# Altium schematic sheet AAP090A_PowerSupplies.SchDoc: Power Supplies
size 431 x 279 mm; Date: Not shown in title block; ApprovedBy: Not shown in title block; CheckedBy: Not shown in title block; Author: Not shown in title block; CompanyName: Not shown in title block; DrawnBy: LDN; Engineer: Not shown in title block; Organization: Not shown in title block; Address1: Not shown in title block; Address2: Not shown in title block; Address3: Not shown in title block; Address4: Not shown in title block; DocumentNumber: 5; Revision: Use project parameter SCH_Rev; SheetNumber: 5; SheetTotal: 6; PageSetup: Record=PageOptions¦CenterHorizontal=True¦CenterVertical=True¦PrintScale=1.00¦XCorrection=1.00¦YCorrection=1.00¦PrintKind=0¦BorderSize=5000000¦LeftOffset=0¦BottomOffset=0¦Orientation=2¦PaperLength=1000¦PaperWidth=1000¦Scale=100¦PaperSource=15¦PrintQuality=600¦MediaType=1¦DitherType=10¦PaperKind=Letter¦PrintScaleMode=1
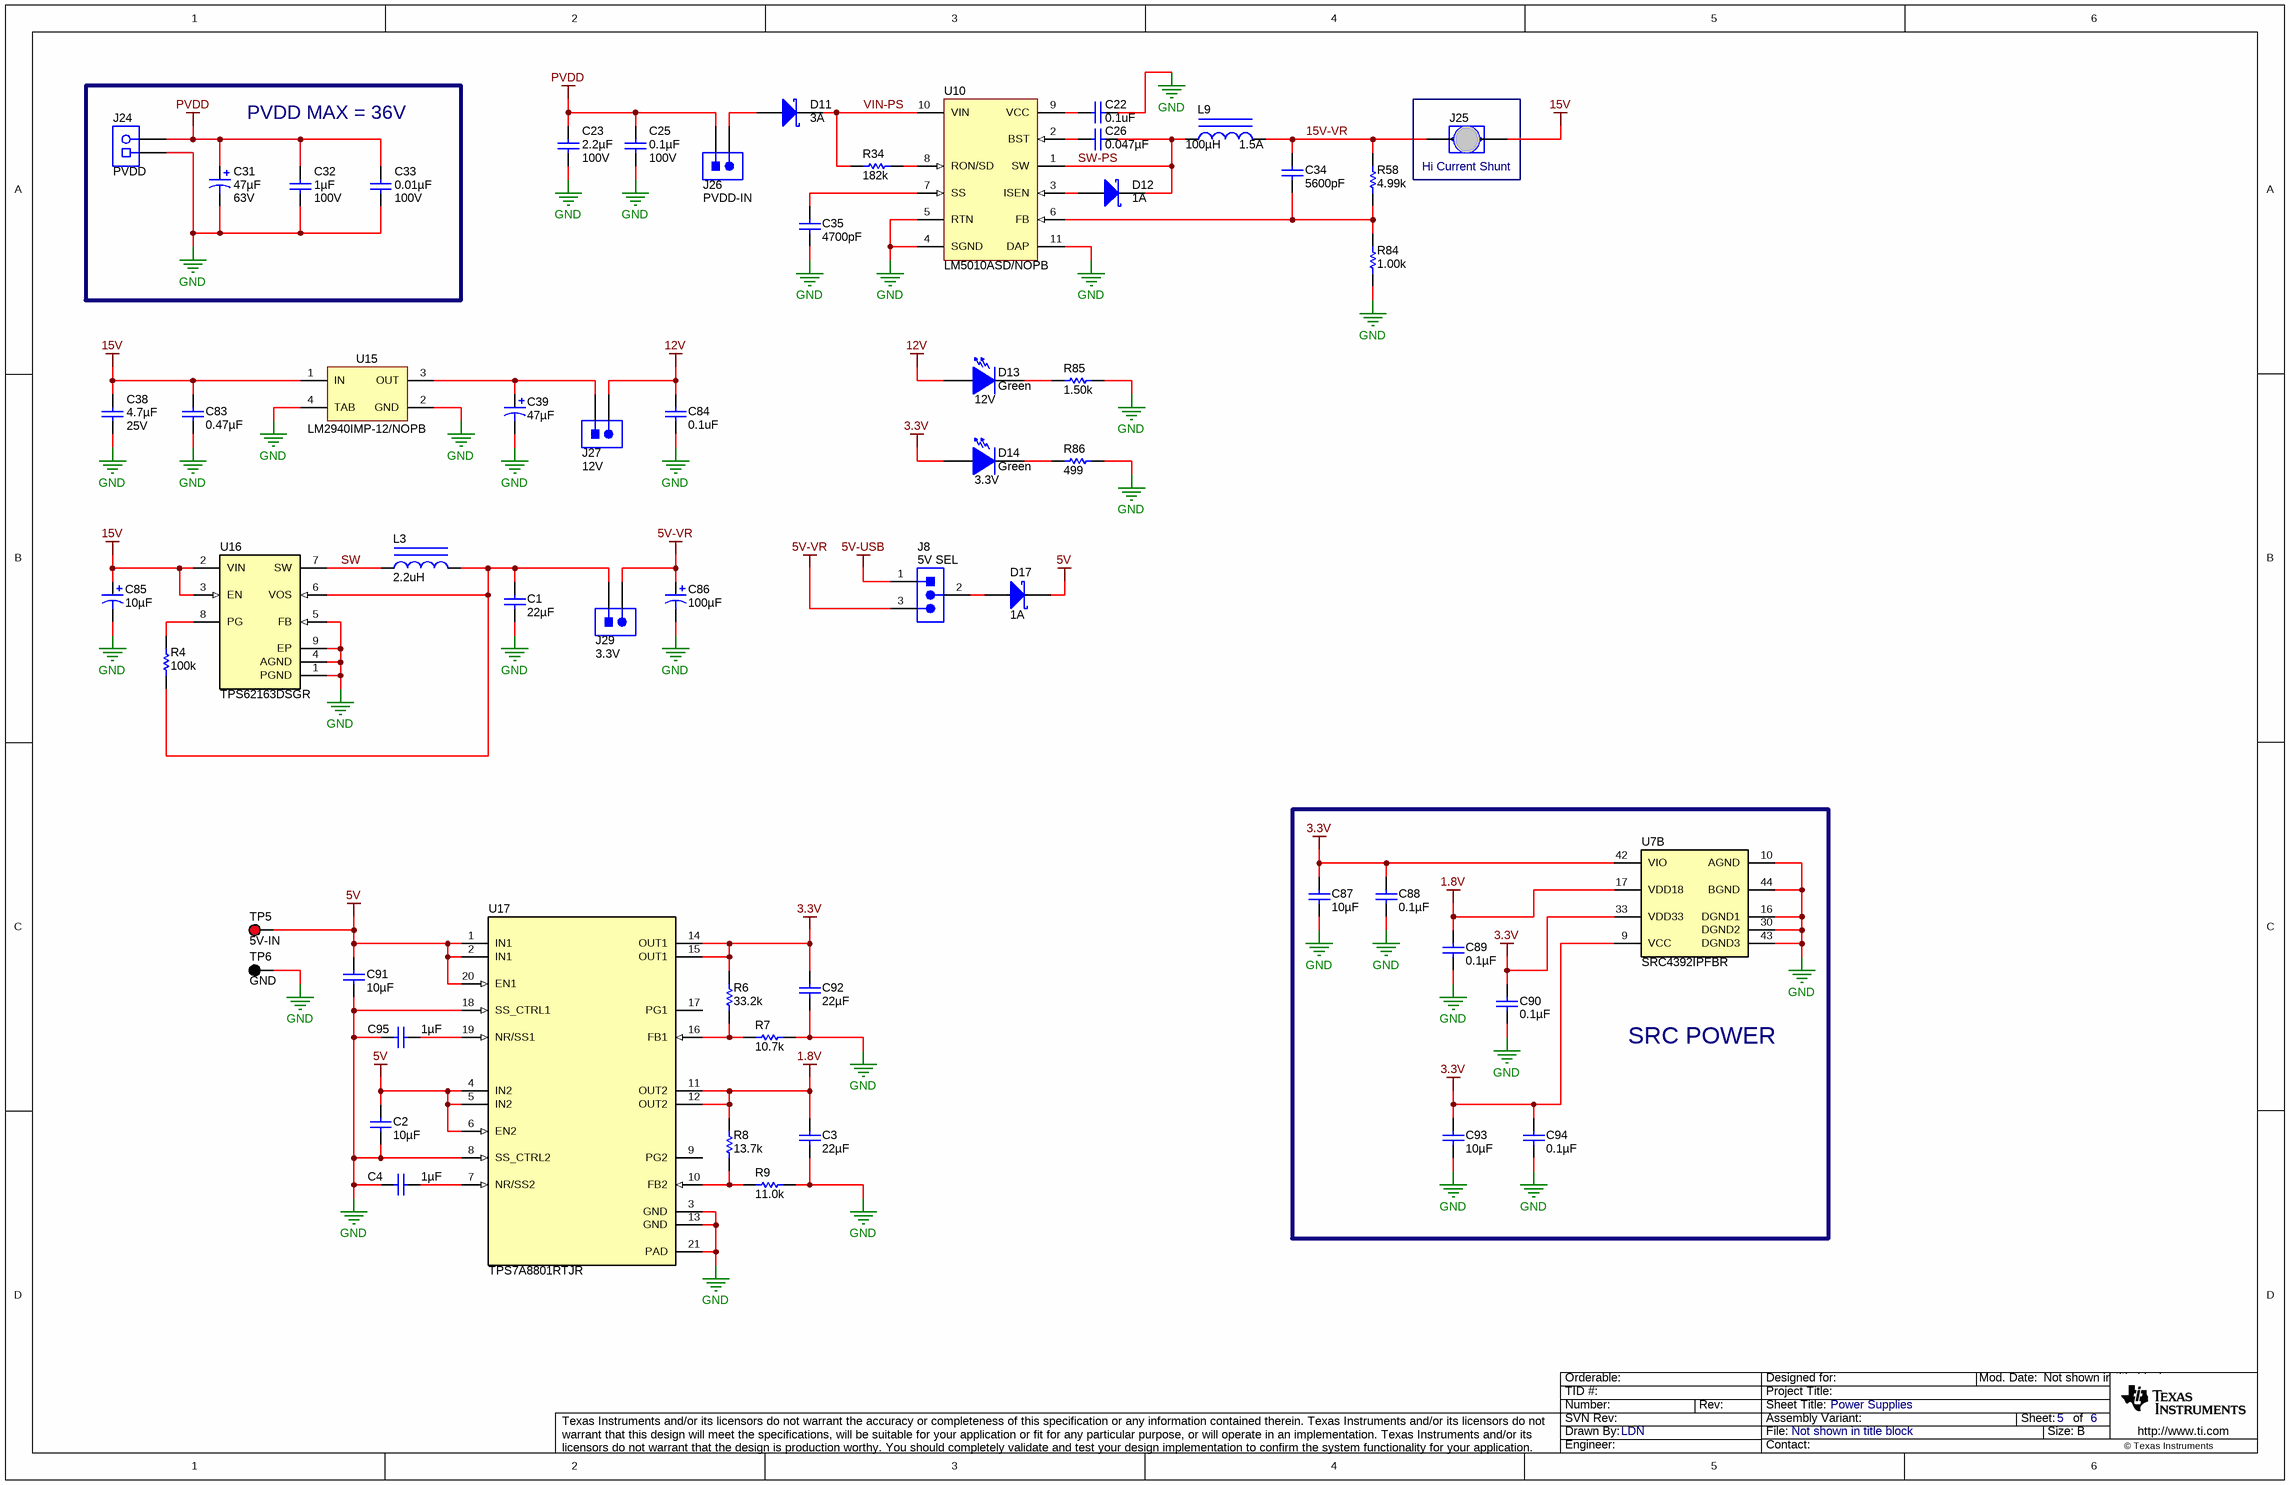
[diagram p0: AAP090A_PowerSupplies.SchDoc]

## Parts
C1  ValueDisplayed: 22µF  [0805_KTR]  (hidden comment: GRM21BZ71A226ME15L)
C2  ValueDisplayed: 10µF  [0603L]  (hidden comment: GRM188R61A106ME69D)
C3  ValueDisplayed: 22µF  [0805_KTR]  (hidden comment: GRM21BZ71A226ME15L)
C4  ValueDisplayed: 1µF  [0603L]  (hidden comment: GRM188R71C105KA12D)
C22  value 0.1uF  [0603L]  (hidden comment: C0603C104K5RACTU)
C23  ValueDisplayed: 2.2µF  Value2: 100V  [1210_210L]  (hidden comment: C1210C225K1RACTU)
C25  ValueDisplayed: 0.1µF  Value2: 100V  [0603L]  (hidden comment: GRM188R72A104KA35J)
C26  ValueDisplayed: 0.047µF  [0402L]  (hidden comment: GRM155R71E473KA88D)
C31  ValueDisplayed: 47µF  Value2: 63V  [SM_RADIAL_F]  (hidden comment: +)
C32  ValueDisplayed: 1µF  Value2: 100V  [1206_180L]  (hidden comment: GRM31CR72A105KA01L)
C33  ValueDisplayed: 0.01µF  Value2: 100V  [0603L]  (hidden comment: 06031C103KAT2A)
C34  ValueDisplayed: 5600pF  [0603L]  (hidden comment: GRM188R71H562KA01D)
C35  ValueDisplayed: 4700pF  [0603L]  (hidden comment: C0603X472K5RACTU)
C38  ValueDisplayed: 4.7µF  Value2: 25V  [1206_180L]  (hidden comment: GRM31CR71E475KA88L)
C39  ValueDisplayed: 47µF  [SM_RADIAL_D]  (hidden comment: +)
C83  ValueDisplayed: 0.47µF  [0603L]  (hidden comment: GRM188R71E474KA12D)
C84  value 0.1uF  [0603L]  (hidden comment: C0603C104K5RACTU)
C85  ValueDisplayed: 10µF  [SM_RADIAL_B]  (hidden comment: +)
C86  ValueDisplayed: 100µF  [SM_RADIAL_C]  (hidden comment: +)
C87  ValueDisplayed: 10µF  [0603L]  (hidden comment: GRM188R61A106ME69D)
C88  ValueDisplayed: 0.1µF  [0402L]  (hidden comment: GRM155R71A104KA01D)
C89  ValueDisplayed: 0.1µF  [0402L]  (hidden comment: GRM155R71A104KA01D)
C90  ValueDisplayed: 0.1µF  [0402L]  (hidden comment: GRM155R71A104KA01D)
C91  ValueDisplayed: 10µF  [0603L]  (hidden comment: GRM188R61A106ME69D)
C92  ValueDisplayed: 22µF  [0805_KTR]  (hidden comment: GRM21BZ71A226ME15L)
C93  ValueDisplayed: 10µF  [0603L]  (hidden comment: GRM188R61A106ME69D)
C94  ValueDisplayed: 0.1µF  [0402L]  (hidden comment: GRM155R71A104KA01D)
C95  ValueDisplayed: 1µF  [0603L]  (hidden comment: GRM188R71C105KA12D)
D11  Value1: 3A  [SMA]  (hidden comment: SK310A-TP)
D12  Value1: 1A  [SMA]  (hidden comment: B1100-13-F)
D13  12V  value Green  [LED_LTST-C171]
D14  3.3V  value Green  [LED_LTST-C171]
D17  Value1: 1A  [SMA]  (hidden comment: B1100-13-F)
J8  5V SEL  [PBC03SAAN]
J24  PVDD  [Pomona_6883]
J25  S1911-46R  [HARWIN_S1911-46R]  (value not drawn)
J26  PVDD-IN  [Sullins_PBC02SAAN]
J27  12V  [Sullins_PBC02SAAN]
J29  3.3V  [Sullins_PBC02SAAN]
L3  ValueDisplayed: 2.2uH  [VLCF4020]  (hidden comment: VLCF4020T-2R2N1R7)
L9  ValueDisplayed: 100µH  Value2: 1.5A  [WE-PD_1050]  (hidden comment: 7447714101)
R4  ValueDisplayed: 100k  [0603L]  (hidden comment: RC0603FR-07100KL)
R6  ValueDisplayed: 33.2k  [0603L]  (hidden comment: RC0603FR-0733K2L)
R7  ValueDisplayed: 10.7k  [0603L]  (hidden comment: RC0603FR-0710K7L)
R8  ValueDisplayed: 13.7k  [0603L]  (hidden comment: RC0603FR-0713K7L)
R9  ValueDisplayed: 11.0k  [0603L]  (hidden comment: RC0603FR-0711KL)
R34  ValueDisplayed: 182k  [0805_KTR]  (hidden comment: ERJ-6ENF1823V)
R58  ValueDisplayed: 4.99k  [0402L]  (hidden comment: RC0402FR-074K99L)
R84  ValueDisplayed: 1.00k  [0402L]  (hidden comment: RC0402FR-071KL)
R85  ValueDisplayed: 1.50k  [0603L]  (hidden comment: RC0603FR-071K5L)
R86  ValueDisplayed: 499  [0603L]  (hidden comment: RC0603FR-07499RL)
TP5  5V-IN  [Keystone5010]
TP6  GND  [Keystone5011]
U7  SRC4392IPFBR  [PFB0048A_N]  (part B of 2)
U10  LM5010ASD/NOPB  [SDC10A]
U15  LM2940IMP-12/NOPB  [MP04A_N]
U16  TPS62163DSGR  [DSG0008A]
U17  TPS7A8801RTJR  [RTJ0020D]

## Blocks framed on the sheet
PVDD MAX = 36V: C31-C33 J24
Hi Current Shunt: J25
SRC POWER: C87-C90 C93 C94 U7

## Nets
1.8V: C3.1 C89.2 R8.1 U7.17(VDD18) U17.11(OUT2) U17.12(OUT2)
3.3V: C87.1 C88.2 C90.2 C92.1 C93.1 C94.2 D14.1(A) R6.1 U7.9(VCC) U7.33(VDD33) U7.42(VIO) U17.14(OUT1) U17.15(OUT1)
5V: C2.1 C91.1 D17.1(K) TP5.1 U17.1(IN1) U17.2(IN1) U17.4(IN2) U17.5(IN2) U17.6(EN2) U17.20(EN1)
5V-USB: J8.1
5V-VR: C86.1(+) J8.3 J29.2
12V: C84.2 D13.1(A) J27.2
15V: C38.1 C83.1 C85.1(+) J25.2 U15.1(IN) U16.2(VIN) U16.3(EN)
GND: C1.2 C2.2 C3.2 C4.1 C22.2 C23.2 C25.2 C31.2(-) C32.1 C33.2 C35.2 C38.2 C39.2(-) C83.2 C84.1 C85.2(-) C86.2(-) C87.2 C88.1 C89.1 C90.1 C91.2 C92.2 C93.2 C94.1 C95.1 J24.1 R7.1 R9.1 R84.1 R85.2 R86.2 TP6.1 U7.10(AGND) U7.16(DGND1) U7.30(DGND2) U7.43(DGND3) U7.44(BGND) U10.4(SGND) U10.5(RTN) U10.11(DAP) U15.2(GND) U15.4(TAB) U16.1(PGND) U16.4(AGND) U16.5(FB) U16.9(EP) U17.3(GND) U17.8(SS_CTRL2) U17.13(GND) U17.18(SS_CTRL1) U17.21(PAD)
PVDD: C23.1 C25.1 C31.1(+) C32.2 C33.1 J24.2 J26.1
15V-VR: C34.1 J25.1 L9.2 R58.2
SW: L3.1 U16.7(SW)
SW-PS: C26.2 D12.1(K) L9.1 U10.1(SW)
VIN-PS: D11.1(K) R34.1 U10.10(VIN)
NetC1_1: C1.1 J29.1 L3.2 R4.1 U16.6(VOS)
NetC4_2: C4.2 U17.7(NR/SS2)
NetC22_1: C22.1 U10.9(VCC)
NetC26_1: C26.1 U10.2(BST)
NetC34_2: C34.2 R58.1 R84.2 U10.6(FB)
NetC35_1: C35.1 U10.7(SS)
NetC39_1: C39.1(+) J27.1 U15.3(OUT)
NetC95_2: C95.2 U17.19(NR/SS1)
NetD11_2: D11.2(A) J26.2
NetD12_2: D12.2(A) U10.3(ISEN)
NetD13_2: D13.2(K) R85.1
NetD14_2: D14.2(K) R86.1
NetD17_2: D17.2(A) J8.2
NetR4_2: R4.2 U16.8(PG)
NetR6_2: R6.2 R7.2 U17.16(FB1)
NetR8_2: R8.2 R9.2 U17.10(FB2)
NetR34_2: R34.2 U10.8(RON/SD)

Not connected (* = marked no-connect by the designer): U17 9(PG2) 17(PG1)

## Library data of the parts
C1 C3 C92 = GRM21BZ71A226ME15L: CAP, CERM, 22 µF, 10 V, +/- 20%, X7R, 0805; Manufacturer: MuRata; Polarized: N; CompType: Capacitor; Value: 22uF; U/M: EA; Cap_F: 0.000022; Tolerance_%: 20; Value1: Unknown; VDC_V: 10; Value2: 10V; TaMin_C: -55; TaMax_C: 125; Cap_Case: 0805; AEC Category: Q200
C2 C87 C91 C93 = GRM188R61A106ME69D: CAP, CERM, 10 µF, 10 V, +/- 20%, X5R, 0603; Manufacturer: MuRata; Polarized: N; CompType: Capacitor; Value: 10uF; U/M: EA; Cap_F: 0.00001; Tolerance_%: 20; Value1: Unknown; VDC_V: 10; Value2: 10V; TaMin_C: -55; TaMax_C: 85; Cap_Case: 0603; AEC Category: Q200
C4 C95 = GRM188R71C105KA12D: CAP, CERM, 1 µF, 16 V, +/- 10%, X7R, 0603; Manufacturer: MuRata; Polarized: N; CompType: Capacitor; Value: 1uF; U/M: EA; Cap_F: 0.000001; Tolerance_%: 10; ESR_ohm: 0.011; Value1: 0.011 ohm; VDC_V: 16; Value2: 16V; TaMin_C: -55; TaMax_C: 125; Cap_Case: 0603; AEC Category: Q200
C22 C84 = C0603C104K5RACTU: CAP, CERM, 0.1 µF, 50 V, +/- 10%, X7R, 0603; Manufacturer: Kemet; Polarized: N; CompType: Capacitor; ValueDisplayed: 0.1µF; U/M: EA; Cap_F: 0.0000001; Tolerance_%: 10; Value1: Unknown; VDC_V: 50; Value2: 50V; TaMin_C: -55; TaMax_C: 125; Cap_Case: 0603; AEC Category: Q200
C23 = C1210C225K1RACTU: CAP, CERM, 2.2 µF, 100 V, +/- 10%, X7R, 1210; Manufacturer: Kemet; Polarized: N; CompType: Capacitor; Value: 2.2uF; U/M: EA; Cap_F: 0.0000022; Tolerance_%: 10; Value1: Unknown; VDC_V: 100; TaMin_C: -55; TaMax_C: 125; Cap_Case: 1210; SizeArea_mm2: 8; SizeAreaWB_mm2: 14.7; SizeX_mm: 3.2; SizeY_mm: 2.5; SizeZ_mm: 2.1; AEC Category: Q200
C25 = GRM188R72A104KA35J: CAP, CERM, 0.1 µF, 100 V, +/- 10%, X7R, 0603; Manufacturer: MuRata; Polarized: N; CompType: Capacitor; Value: 0.1uF; U/M: EA; Cap_F: 0.0000001; Tolerance_%: 10; Value1: Unknown; VDC_V: 100; TaMin_C: -55; TaMax_C: 125; Cap_Case: 0603; AEC Category: Q200
C26 = GRM155R71E473KA88D: CAP, CERM, 0.047 µF, 25 V, +/- 10%, X7R, 0402; Manufacturer: MuRata; Polarized: N; CompType: Capacitor; Value: 0.047uF; U/M: EA; Cap_F: 0.000000047; Tolerance_%: 10; Value1: Unknown; VDC_V: 25; Value2: 25V; TaMin_C: -55; TaMax_C: 125; Cap_Case: 0402; AEC Category: Q200
C31 = EEE-FK1J470P: CAP, AL, 47 µF, 63 V, +/- 20%, 0.65 ohm, SMD; Manufacturer: Panasonic; Polarized: Y; CompType: Capacitor; Value: 47uF; U/M: EA; Cap_F: 0.000047; Tolerance_%: 20; VDC_V: 63; ESR_ohm: 0.65; IRMS_A: 0.25; TaMin_C: -55; TaMax_C: 105; Cap_Case: F; AEC Category: Q200
C32 = GRM31CR72A105KA01L: CAP, CERM, 1 µF, 100 V, +/- 10%, X7R, 1206; Manufacturer: MuRata; Polarized: N; CompType: Capacitor; Value: 1uF; U/M: EA; Cap_F: 0.000001; Tolerance_%: 10; Value1: Unknown; VDC_V: 100; TaMin_C: -55; TaMax_C: 125; Cap_Case: 2220; SizeArea_mm2: 5.12; SizeAreaWB_mm2: 10.92; SizeX_mm: 3.2; SizeY_mm: 1.6; SizeZ_mm: 1.8; AEC Category: Q200
C33 = 06031C103KAT2A: CAP, CERM, 0.01 µF, 100 V, +/- 10%, X7R, 0603; Manufacturer: AVX; Polarized: N; CompType: Capacitor; Value: 0.01uF; U/M: EA; Cap_F: 0.00000001; Tolerance_%: 10; ESR_ohm: 0.098; Value1: 0.098 ohm; VDC_V: 100; TaMin_C: -55; TaMax_C: 125; Cap_Case: 0603; AEC Category: Q200
C34 = GRM188R71H562KA01D: CAP, CERM, 5600 pF, 50 V, +/- 10%, X7R, 0603; Manufacturer: MuRata; Polarized: N; CompType: Capacitor; Value: 5600pF; U/M: EA; Cap_F: 0.0000000056; Tolerance_%: 10; Value1: Unknown; VDC_V: 50; Value2: 50V; TaMin_C: -55; TaMax_C: 125; Cap_Case: 0603; AEC Category: Q200
C35 = C0603X472K5RACTU: CAP, CERM, 4700 pF, 50 V, +/- 10%, X7R, 0603; Manufacturer: Kemet; Polarized: N; CompType: Capacitor; Value: 4700pF; U/M: EA; Cap_F: 0.0000000047; Tolerance_%: 10; Value1: Unknown; VDC_V: 50; Value2: 50V; TaMin_C: -55; TaMax_C: 125; Cap_Case: 0603; AEC Category: Q200
C38 = GRM31CR71E475KA88L: CAP, CERM, 4.7 µF, 25 V, +/- 10%, X7R, 1206; Manufacturer: MuRata; Polarized: N; CompType: Capacitor; Value: 4.7uF; U/M: EA; Cap_F: 0.0000047; Tolerance_%: 10; Value1: Unknown; VDC_V: 25; TaMin_C: -55; TaMax_C: 125; Cap_Case: 1206; SizeArea_mm2: 5.12; SizeAreaWB_mm2: 10.92; SizeX_mm: 3.2; SizeY_mm: 1.6; SizeZ_mm: 1.8; AEC Category: Q200
C39 = EEE-FK1C470P: CAP, AL, 47 µF, 16 V, +/- 20%, 0.36 ohm, SMD; Manufacturer: Panasonic; Polarized: Y; CompType: Capacitor; Value: 47uF; U/M: EA; Cap_F: 0.000047; Tolerance_%: 20; VDC_V: 16; Value2: 16V; ESR_ohm: 0.36; IRMS_A: 0.24; TaMin_C: -55; TaMax_C: 105; Cap_Case: D; AEC Category: Q200
C83 = GRM188R71E474KA12D: CAP, CERM, 0.47 µF, 25 V, +/- 10%, X7R, 0603; Manufacturer: MuRata; Polarized: N; CompType: Capacitor; Value: 0.47uF; U/M: EA; Cap_F: 0.00000047; Tolerance_%: 10; Value1: Unknown; VDC_V: 25; Value2: 25V; TaMin_C: -55; TaMax_C: 125; Cap_Case: 0603; AEC Category: Q200
C85 = EEE-FK1C100R: CAP, AL, 10 µF, 16 V, +/- 20%, 1.35 ohm, SMD; Manufacturer: Panasonic; Polarized: Y; CompType: Capacitor; Value: 10uF; U/M: EA; Cap_F: 0.00001; Tolerance_%: 20; VDC_V: 16; Value2: 16V; ESR_ohm: 1.35; IRMS_A: 0.09; TaMin_C: -55; TaMax_C: 105; Cap_Case: B; AEC Category: Q200
C86 = EEE-FK0J101UR: CAP, AL, 100 µF, 6.3 V, +/- 20%, 0.7 ohm, SMD; Manufacturer: Panasonic; Polarized: Y; CompType: Capacitor; Value: 100uF; U/M: EA; Cap_F: 0.0001; Tolerance_%: 20; Value1: 0.7 ohm; VDC_V: 6.3; Value2: 6.3V; ESR_ohm: 0.7; IRMS_A: 0.16; TaMin_C: -55; TaMax_C: 105; Cap_Case: C; AEC Category: Q200
C88-C90 C94 = GRM155R71A104KA01D: CAP, CERM, 0.1 µF, 10 V, +/- 10%, X7R, 0402; Manufacturer: MuRata; Polarized: N; CompType: Capacitor; Value: 0.1uF; U/M: EA; Cap_F: 0.0000001; Tolerance_%: 10; Value1: Unknown; Value2: 10V; TaMin_C: -55; TaMax_C: 125; Cap_Case: 0402; AEC Category: Q200
D11 = SK310A-TP: Diode, Schottky, 100 V, 3 A, SMA; Manufacturer: Micro Commercial Components; U/M: EA; Vf_V: 0.85; Value: 100V; Value2: 0.85V; Io_A: 3; Vr_V: 100; TJmax_C: 125; RJC_CperW: 10; AEC Category: Q101
D12 D17 = B1100-13-F: Diode, Schottky, 100 V, 1 A, SMA; Manufacturer: Diodes Inc.; U/M: EA; Vf_V: 0.79; Value: 100V; Value2: 0.79V; Io_A: 1; Vr_V: 100; TJmax_C: 150; RJC_CperW: 25; AEC Category: Q101
D13 D14 = LTST-C171GKT: LED, Green, SMD; Manufacturer: Lite-On; Type: AlInGaP; Vf_V: 2.1; Value2: 2.1V; Io_A: 20; Value1: W; U/M: EA
J8 = PBC03SAAN: Header, 100mil, 3x1, Gold, TH; Manufacturer: Sullins Connector Solutions; SymbolCreator: a0799628; Green_Lifecycle: Not Set; Green_REACh: Incomplete
J24 = CMP-0075104-1: Dual Binding Posts with Base, 2x1, TH; Manufacturer: Pomona Electronics; PartNumber: 6883; CNHeader: False; Green_Lifecycle: Not Set; Green_REACh: Incomplete; CompType: Connector
J25 = CMP-0075020-1: JUMPER TIN SMD; Manufacturer: Harwin; CNHeader: False; Green_Lifecycle: Active; Green_REACh: Passed; CompType: Jumper SMT
J26 J27 J29 = PBC02SAAN: Header, 100mil, 2x1, Gold, TH; Manufacturer: Sullins Connector Solutions; SymbolCreator: a0412235; Pitch_mm: 2.54; Gender: Male; Shrouded: N; Row_Count: 1; Current_A: 3; Voltage_V: 1800; Cert_UL: Y
L3 = CMP-0062895-1: Inductor, Shielded, Ferrite, 2.2 uH, 1.72 A, 0.059 ohm, SMD; Manufacturer: TDK; Isat: 1.72A @ 30% inductance drop; Irms: 2.19A @ 40C rise; Green_Lifecycle: Active; SizeAreaWB_mm2: 25; DCR_ohm: 0.059; Green_REACh: Passed; Value: 2.2uH; Imax_A: 1.72A; SizeZ_mm: 2; SizeX_mm: 4; SizeArea_mm2: 16; Ind_H: 2.2µH; AEC Category: Q200
L9 = 7447714101: Inductor, Shielded Drum Core, Ferrite, 100 µH, 1.5 A, 0.165 ohm, SMD; Manufacturer: Wurth Elektronik; Value: 100uH; Ind_H: 100.0E-6; Imax_A: 1.5; Irms: 1.5A @ 40C rise; Isat: 1.75A @ 10% inductance drop; DCR_ohm: 0.165; AEC Category: Q200
R4 = RC0603FR-07100KL: RES, 100 k, 1%, 0.1 W, 0603; Manufacturer: Yageo America; CompType: Resistor; Value: 100k; Res_ohm: 100000; Tolerance_%: 1; Power_W: 0.1; Value2: 0.1W; VDC_V: 150; TempCo: 200 ppm/C; EIA_Code: E96; U/M: EA; AEC Category: Q200; SizeArea_mm2: 1.28; SizeX_mm: 1.6; SizeY_mm: 0.8; Green_Lifecycle: Active; Green_REACh: Passed
R6 = RC0603FR-0733K2L: RES, 33.2 k, 1%, 0.1 W, 0603; Manufacturer: Yageo America; CompType: Resistor; Value: 33.2k; Res_ohm: 33200; Value_Code: 33k2; Tolerance_%: 1; Power_W: 0.1; Value2: 0.1W; VDC_V: 150; TempCo: 200 ppm/C; EIA_Code: E96; U/M: EA; AEC Category: Q200; SizeArea_mm2: 1.28; SizeX_mm: 1.6; SizeY_mm: 0.8; Green_Lifecycle: Active; Green_REACh: Passed
R7 = RC0603FR-0710K7L: RES, 10.7 k, 1%, 0.1 W, 0603; Manufacturer: Yageo America; CompType: Resistor; Value: 10.7k; Res_ohm: 10700; Value_Code: 10k7; Tolerance_%: 1; Power_W: 0.1; Value2: 0.1W; VDC_V: 150; TempCo: 200 ppm/C; EIA_Code: E96; U/M: EA; AEC Category: Q200; SizeArea_mm2: 1.28; SizeX_mm: 1.6; SizeY_mm: 0.8
R8 = RC0603FR-0713K7L: RES, 13.7 k, 1%, 0.1 W, 0603; Manufacturer: Yageo America; CompType: Resistor; Value: 13.7k; Res_ohm: 13700; Value_Code: 13k7; Tolerance_%: 1; Power_W: 0.1; Value2: 0.1W; VDC_V: 150; TempCo: 200 ppm/C; EIA_Code: E96; U/M: EA; AEC Category: Q200; SizeArea_mm2: 1.28; SizeX_mm: 1.6; SizeY_mm: 0.8; Green_Lifecycle: Active; Green_REACh: Passed
R9 = RC0603FR-0711KL: RES, 11.0 k, 1%, 0.1 W, 0603; Manufacturer: Yageo America; CompType: Resistor; Value: 11.0k; Res_ohm: 11000; Value_Code: 11k0; Tolerance_%: 1; Power_W: 0.1; Value2: 0.1W; VDC_V: 150; TempCo: 200 ppm/C; EIA_Code: E96; U/M: EA; AEC Category: Q200; SizeArea_mm2: 1.28; SizeX_mm: 1.6; SizeY_mm: 0.8; Green_Lifecycle: Active; Green_REACh: Passed
R34 = ERJ-6ENF1823V: RES, 182 k, 1%, 0.125 W, 0805; Manufacturer: Panasonic; CompType: Resistor; Value: 182k; Res_ohm: 182000; Tolerance_%: 1; Power_W: 0.125; Value2: 0.125W; TempCo: 100 ppm/C; EIA_Code: E96; U/M: EA; AEC Category: Q200
R58 = RC0402FR-074K99L: RES, 4.99 k, 1%, 0.063 W, 0402; Manufacturer: Yageo America; CompType: Resistor; Value: 4.99k; Res_ohm: 4990; Value_Code: 4k99; Tolerance_%: 1; Power_W: 0.063; Value2: 0.063W; VDC_V: 50; TempCo: 100 ppm/C; EIA_Code: E96; U/M: EA; AEC Category: Q200; AEC Qualified: N; SizeArea_mm2: 0.5; SizeZ_mm: 0.6; Green_Lifecycle: Active; Green_REACh: Passed
R84 = RC0402FR-071KL: RES, 1.00 k, 1%, 0.0625 W, 0402; Manufacturer: Yageo America; CompType: Resistor; Value: 1.00k; Res_ohm: 1000; Value_Code: 1k00; Tolerance_%: 1; Power_W: 0.0625; VDC_V: 50; TempCo: 100 ppm/C; EIA_Code: E96; U/M: EA; AEC Category: Q200; AEC Qualified: N; SizeArea_mm2: 0.5; SizeZ_mm: 0.6; Green_Lifecycle: Active; Green_REACh: Passed
R85 = RC0603FR-071K5L: RES, 1.50 k, 1%, 0.1 W, 0603; Manufacturer: Yageo America; CompType: Resistor; Value: 1.50k; Res_ohm: 1500; Value_Code: 1k50; Tolerance_%: 1; Power_W: 0.1; Value2: 0.1W; VDC_V: 150; TempCo: 200 ppm/C; EIA_Code: E96; U/M: EA; AEC Category: Q200; SizeArea_mm2: 1.28; SizeX_mm: 1.6; SizeY_mm: 0.8; Green_Lifecycle: Active; Green_REACh: Passed
R86 = RC0603FR-07499RL: RES, 499, 1%, 0.1 W, 0603; Manufacturer: Yageo America; CompType: Resistor; Value: 499; Value_Code: 499R; Tolerance_%: 1; Power_W: 0.1; Value2: 0.1W; VDC_V: 150; TempCo: 200 ppm/C; EIA_Code: E96; U/M: EA; AEC Category: Q200; SizeArea_mm2: 1.28; SizeX_mm: 1.6; SizeY_mm: 0.8; Green_Lifecycle: Active; Green_REACh: Passed
TP5 = 5010: Test Point, Multipurpose, Red, TH; Manufacturer: Keystone; CompType: Test Point Loop; ContactFinish: Silver; Green_Lifecycle: Active; Green_REACh: Passed
TP6 = 5011: Test Point, Multipurpose, Black, TH; Manufacturer: Keystone; CompType: Test Point Loop; ContactFinish: Silver; Green_Lifecycle: Active; Green_REACh: Passed
U7 = SRC4392IPFBR: 216 SPS High-end Combo Sample Rate Converter, 144dB, 1.8 / 3.3V, -40 to 85 degC, 48-Pin TQFP (PFB), Green (RoHS & no Sb/Br); Manufacturer: Texas Instruments; Alternate PartNumber: Equivalent; Sample Rate (max)(SPS): 216; # SRC Channels: 2; Digital Audio Interface: AES/EBU, S/PDIF; Dynamic Range(dB): 144; Digital Supply (up to 5 V)(V): 1.65 - 1.95, 3 - 3.6; THD+N(dB): -140; Control Mode: SW (SPI), H/W; Power Supply(V): 1.8, 3.3; Control Interface: SPI, I2C; Audio Data Format: Normal, I2S"
U10 = LM5010ASD/NOPB: High Voltage 1A Step Down Switching Regulator, 10-pin LLP, Pb-Free; Manufacturer: Texas Instruments; PackageTopMarking: NS*UZXYTT*L00065B; PowerWise: N; CompType: Switcher
U15 = LM2940IMP-12/NOPB: 1A Low Dropout Regulator, 4-pin SOT-223, Pb-Free; Manufacturer: Texas Instruments; PackageTopMarking: XYTT*L56B; PowerWise: N; CompType: LDO IC
U16 = TPS62163DSGR: Buck Step Down Regulator with 3 to 17 V Input and 5 V Output, -40 to 85 degC, 8-Pin WSON (DSG), Green (RoHS & no Sb/Br); Manufacturer: Texas Instruments; Alternate PartNumber: Equivalent; Duty Cycle(Max)(%): 100; Iout(Max)(A): 1; Iq(Typ)(mA): 0.017; Preset Vout(V): 5; Rating: Catalog; SubFamily: Step-Down Regulator; Switch Current Limit(Typ)(A): 1.8; Synchronous Rectification: TRUE; Vin(Max)(V): 17; Vin(Min)(V): 3
U17 = CMP-0073732-2: Dual, 1-A, Low Noise (3.8-uVRMS), LDO Voltage Regulator, RTJ0020D (WQFN-20); Alternate PartNumber: TPS7A8801RTJT; Alternate Manufacturer: Texas Instruments; Green_Lifecycle: Active; SizeAreaWB_mm2: 25.0; Green_REACh: Passed; U/M: EA; SizeZ_mm: 0.8; SizeX_mm: 4.0; SizeArea_mm2: 16.0; CompType: IC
